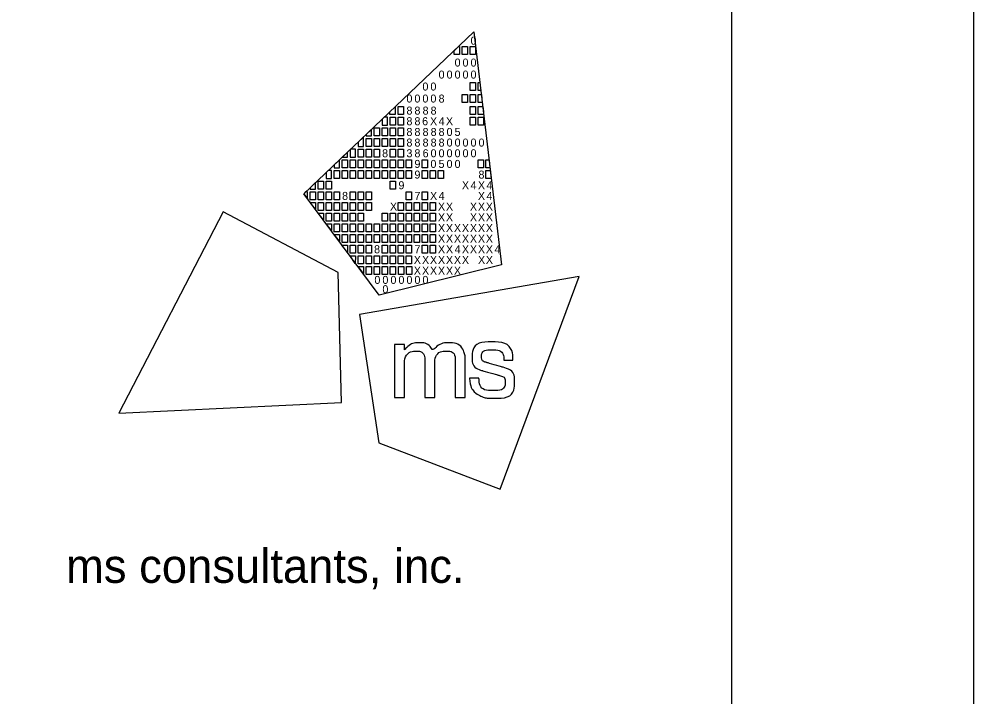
# Model space of a CAD drawing. Extents: x 0 to 34, y 0 to 22.
# Drawn here: x 32.03 to 34, y 2.714 to 4.112 of the extents above; entities that cross this region are included whole.
import ezdxf

# ---------------------------------------------------------------- set-up
doc = ezdxf.new("R2010")
doc.units = 0
for name, color, linetype in [('SH_Border', 7, 'Continuous'), ('SH_Cut_Line', 7, 'Continuous'), ('SH_Data', 7, 'Continuous')]:
    doc.layers.add(name, color=color, linetype=linetype)

msp = doc.modelspace()

# ---------------------------------------------------------------- linework, layer by layer
at = {"layer": 'SH_Border'}
msp.add_lwpolyline([(1.5, 21.5), (33.5, 21.5), (33.5, 0.5), (1.5, 0.5)], close=True, dxfattribs=at)
at = {"layer": 'SH_Cut_Line'}
msp.add_lwpolyline([(0, 0), (34, 0), (34, 22), (0, 22)], close=True, dxfattribs=at)
at = {"layer": 'SH_Data'}
for p, q in [((32.6175, 3.7519), (32.9688, 4.0861)), ((32.9688, 4.0861), (32.9688, 4.0861)), ((32.9688, 4.0861), (33.0253, 3.6052)), ((32.773, 3.543), (32.6175, 3.7519)), ((33.0253, 3.6052), (32.773, 3.543)), ((32.75, 3.5), (32.75, 3.5))]:
    msp.add_line(p, q, dxfattribs=at)
for points in [[(32.9279, 4.0472), (32.9369, 4.0558), (32.9389, 4.0558), (32.9389, 4.0393), (32.9279, 4.0393)], [(32.9444, 4.0558), (32.9554, 4.0558), (32.9554, 4.0393), (32.9444, 4.0393)], [(32.9609, 4.0558), (32.9719, 4.0558), (32.9719, 4.0393), (32.9609, 4.0393)], [(32.9606, 3.9815), (32.9716, 3.9815), (32.9716, 3.965), (32.9606, 3.965)], [(32.9771, 3.9815), (32.9811, 3.9815), (32.983, 3.965), (32.9771, 3.965)], [(32.9441, 3.9567), (32.9551, 3.9567), (32.9551, 3.9402), (32.9441, 3.9402)], [(32.9606, 3.9567), (32.9716, 3.9567), (32.9716, 3.9402), (32.9606, 3.9402)], [(32.9771, 3.9567), (32.984, 3.9567), (32.9859, 3.9402), (32.9771, 3.9402)], [(32.7953, 3.9211), (32.8064, 3.9316), (32.8064, 3.9154), (32.7953, 3.9154)], [(32.8123, 3.9319), (32.8233, 3.9319), (32.8233, 3.9154), (32.8123, 3.9154)], [(32.9606, 3.9319), (32.9716, 3.9319), (32.9716, 3.9154), (32.9606, 3.9154)], [(32.9771, 3.9319), (32.9869, 3.9319), (32.9881, 3.9218), (32.9881, 3.9154), (32.9771, 3.9154)], [(32.7958, 3.9099), (32.8068, 3.9099), (32.8068, 3.8934), (32.7958, 3.8934)], [(32.8123, 3.9099), (32.8233, 3.9099), (32.8233, 3.8934), (32.8123, 3.8934)], [(32.9606, 3.9099), (32.9716, 3.9099), (32.9716, 3.8934), (32.9606, 3.8934)], [(32.9771, 3.9099), (32.9881, 3.9099), (32.9881, 3.8934), (32.9771, 3.8934)], [(32.7627, 3.8879), (32.7737, 3.8879), (32.7737, 3.8714), (32.7627, 3.8714)], [(32.7793, 3.8879), (32.7903, 3.8879), (32.7903, 3.8714), (32.7793, 3.8714)], [(32.7958, 3.8879), (32.8068, 3.8879), (32.8068, 3.8714), (32.7958, 3.8714)], [(32.8123, 3.8879), (32.8233, 3.8879), (32.8233, 3.8714), (32.8123, 3.8714)], [(32.7462, 3.8659), (32.7572, 3.8659), (32.7572, 3.8494), (32.7462, 3.8494)], [(32.7627, 3.8659), (32.7737, 3.8659), (32.7737, 3.8494), (32.7627, 3.8494)], [(32.7793, 3.8659), (32.7903, 3.8659), (32.7903, 3.8494), (32.7793, 3.8494)], [(32.7958, 3.8659), (32.8068, 3.8659), (32.8068, 3.8494), (32.7958, 3.8494)], [(32.8123, 3.8659), (32.8233, 3.8659), (32.8233, 3.8494), (32.8123, 3.8494)], [(32.7297, 3.8439), (32.7407, 3.8439), (32.7407, 3.8273), (32.7297, 3.8273)], [(32.7462, 3.8439), (32.7572, 3.8439), (32.7572, 3.8273), (32.7462, 3.8273)], [(32.7627, 3.8439), (32.7737, 3.8439), (32.7737, 3.8273), (32.7627, 3.8273)], [(32.7958, 3.8439), (32.8068, 3.8439), (32.8068, 3.8273), (32.7958, 3.8273)], [(32.8123, 3.8439), (32.8233, 3.8439), (32.8233, 3.8273), (32.8123, 3.8273)], [(32.6967, 3.8218), (32.7077, 3.8218), (32.7077, 3.8053), (32.6967, 3.8053)], [(32.7132, 3.8218), (32.7242, 3.8218), (32.7242, 3.8053), (32.7132, 3.8053)], [(32.7297, 3.8218), (32.7407, 3.8218), (32.7407, 3.8053), (32.7297, 3.8053)], [(32.7462, 3.8218), (32.7572, 3.8218), (32.7572, 3.8053), (32.7462, 3.8053)], [(32.7627, 3.8218), (32.7737, 3.8218), (32.7737, 3.8053), (32.7627, 3.8053)], [(32.7793, 3.8218), (32.7903, 3.8218), (32.7903, 3.8053), (32.7793, 3.8053)], [(32.7958, 3.8218), (32.8068, 3.8218), (32.8068, 3.8053), (32.7958, 3.8053)], [(32.8123, 3.8218), (32.8233, 3.8218), (32.8233, 3.8053), (32.8123, 3.8053)], [(32.8288, 3.8218), (32.8398, 3.8218), (32.8398, 3.8053), (32.8288, 3.8053)], [(32.8618, 3.8218), (32.8728, 3.8218), (32.8728, 3.8053), (32.8618, 3.8053)], [(32.9771, 3.8218), (32.9881, 3.8218), (32.9881, 3.8053), (32.9771, 3.8053)], [(32.9935, 3.8218), (32.9998, 3.8218), (33.0018, 3.8053), (32.9935, 3.8053)], [(32.6802, 3.7998), (32.6912, 3.7998), (32.6912, 3.7833), (32.6802, 3.7833)], [(32.6967, 3.7998), (32.7077, 3.7998), (32.7077, 3.7833), (32.6967, 3.7833)], [(32.7132, 3.7998), (32.7242, 3.7998), (32.7242, 3.7833), (32.7132, 3.7833)], [(32.7297, 3.7998), (32.7407, 3.7998), (32.7407, 3.7833), (32.7297, 3.7833)], [(32.7462, 3.7998), (32.7572, 3.7998), (32.7572, 3.7833), (32.7462, 3.7833)], [(32.7627, 3.7998), (32.7737, 3.7998), (32.7737, 3.7833), (32.7627, 3.7833)], [(32.7793, 3.7998), (32.7903, 3.7998), (32.7903, 3.7833), (32.7793, 3.7833)], [(32.7958, 3.7998), (32.8068, 3.7998), (32.8068, 3.7833), (32.7958, 3.7833)], [(32.8123, 3.7998), (32.8233, 3.7998), (32.8233, 3.7833), (32.8123, 3.7833)], [(32.8288, 3.7998), (32.8398, 3.7998), (32.8398, 3.7833), (32.8288, 3.7833)], [(32.8618, 3.7998), (32.8728, 3.7998), (32.8728, 3.7833), (32.8618, 3.7833)], [(32.8783, 3.7998), (32.8893, 3.7998), (32.8893, 3.7833), (32.8783, 3.7833)], [(32.8947, 3.7998), (32.9057, 3.7998), (32.9057, 3.7833), (32.8947, 3.7833)], [(32.9935, 3.7998), (33.0024, 3.7998), (33.0044, 3.7833), (32.9935, 3.7833)], [(32.6471, 3.7778), (32.6581, 3.7778), (32.6581, 3.7613), (32.6471, 3.7613)], [(32.6637, 3.7778), (32.6747, 3.7778), (32.6747, 3.7613), (32.6637, 3.7613)], [(32.7958, 3.7778), (32.8068, 3.7778), (32.8068, 3.7613), (32.7958, 3.7613)], [(32.6306, 3.7558), (32.6416, 3.7558), (32.6416, 3.7393), (32.6306, 3.7393)], [(32.6471, 3.7558), (32.6581, 3.7558), (32.6581, 3.7393), (32.6471, 3.7393)], [(32.6637, 3.7558), (32.6747, 3.7558), (32.6747, 3.7393), (32.6637, 3.7393)], [(32.6802, 3.7558), (32.6912, 3.7558), (32.6912, 3.7393), (32.6802, 3.7393)], [(32.7132, 3.7558), (32.7242, 3.7558), (32.7242, 3.7393), (32.7132, 3.7393)], [(32.7297, 3.7558), (32.7407, 3.7558), (32.7407, 3.7393), (32.7297, 3.7393)], [(32.7462, 3.7558), (32.7572, 3.7558), (32.7572, 3.7393), (32.7462, 3.7393)], [(32.8288, 3.7558), (32.8398, 3.7558), (32.8398, 3.7393), (32.8288, 3.7393)], [(32.8618, 3.7558), (32.8728, 3.7558), (32.8728, 3.7393), (32.8618, 3.7393)], [(32.6306, 3.7338), (32.6416, 3.7338), (32.6416, 3.72)], [(32.6471, 3.7338), (32.6581, 3.7338), (32.6581, 3.7173), (32.6471, 3.7173)], [(32.6637, 3.7338), (32.6747, 3.7338), (32.6747, 3.7173), (32.6637, 3.7173)], [(32.6802, 3.7338), (32.6912, 3.7338), (32.6912, 3.7173), (32.6802, 3.7173)], [(32.6967, 3.7338), (32.7077, 3.7338), (32.7077, 3.7173), (32.6967, 3.7173)], [(32.7132, 3.7338), (32.7242, 3.7338), (32.7242, 3.7173), (32.7132, 3.7173)], [(32.7297, 3.7338), (32.7407, 3.7338), (32.7407, 3.7173), (32.7297, 3.7173)], [(32.7462, 3.7338), (32.7572, 3.7338), (32.7572, 3.7173), (32.7462, 3.7173)], [(32.8123, 3.7338), (32.8233, 3.7338), (32.8233, 3.7173), (32.8123, 3.7173)], [(32.8288, 3.7338), (32.8398, 3.7338), (32.8398, 3.7173), (32.8288, 3.7173)], [(32.8453, 3.7338), (32.8563, 3.7338), (32.8563, 3.7173), (32.8453, 3.7173)], [(32.8618, 3.7338), (32.8728, 3.7338), (32.8728, 3.7173), (32.8618, 3.7173)], [(32.8783, 3.7338), (32.8893, 3.7338), (32.8893, 3.7173), (32.8783, 3.7173)], [(32.6471, 3.7117), (32.6581, 3.7117), (32.6581, 3.698)], [(32.6637, 3.7117), (32.6747, 3.7117), (32.6747, 3.6952), (32.6637, 3.6952)], [(32.6802, 3.7117), (32.6912, 3.7117), (32.6912, 3.6952), (32.6802, 3.6952)], [(32.6967, 3.7117), (32.7077, 3.7117), (32.7077, 3.6952), (32.6967, 3.6952)], [(32.7132, 3.7117), (32.7242, 3.7117), (32.7242, 3.6952), (32.7132, 3.6952)], [(32.7297, 3.7117), (32.7407, 3.7117), (32.7407, 3.6952), (32.7297, 3.6952)], [(32.7793, 3.7117), (32.7903, 3.7117), (32.7903, 3.6952), (32.7793, 3.6952)], [(32.7958, 3.7117), (32.8068, 3.7117), (32.8068, 3.6952), (32.7958, 3.6952)], [(32.8123, 3.7117), (32.8233, 3.7117), (32.8233, 3.6952), (32.8123, 3.6952)], [(32.8288, 3.7117), (32.8398, 3.7117), (32.8398, 3.6952), (32.8288, 3.6952)], [(32.8453, 3.7117), (32.8563, 3.7117), (32.8563, 3.6952), (32.8453, 3.6952)], [(32.8618, 3.7117), (32.8728, 3.7117), (32.8728, 3.6952), (32.8618, 3.6952)], [(32.8783, 3.7117), (32.8893, 3.7117), (32.8893, 3.6952), (32.8783, 3.6952)], [(32.6637, 3.6897), (32.6747, 3.6897), (32.6747, 3.676)], [(32.6747, 3.6897), (32.6747, 3.6897), (32.6747, 3.6897)], [(32.6802, 3.6897), (32.6912, 3.6897), (32.6912, 3.6732), (32.6802, 3.6732)], [(32.6967, 3.6897), (32.7077, 3.6897), (32.7077, 3.6732), (32.6967, 3.6732)], [(32.7132, 3.6897), (32.7242, 3.6897), (32.7242, 3.6732), (32.7132, 3.6732)], [(32.7297, 3.6897), (32.7407, 3.6897), (32.7407, 3.6732), (32.7297, 3.6732)], [(32.7462, 3.6897), (32.7572, 3.6897), (32.7572, 3.6732), (32.7462, 3.6732)], [(32.7627, 3.6897), (32.7737, 3.6897), (32.7737, 3.6732), (32.7627, 3.6732)], [(32.7793, 3.6897), (32.7903, 3.6897), (32.7903, 3.6732), (32.7793, 3.6732)], [(32.7958, 3.6897), (32.8068, 3.6897), (32.8068, 3.6732), (32.7958, 3.6732)], [(32.8123, 3.6897), (32.8233, 3.6897), (32.8233, 3.6732), (32.8123, 3.6732)], [(32.8288, 3.6897), (32.8398, 3.6897), (32.8398, 3.6732), (32.8288, 3.6732)], [(32.8453, 3.6897), (32.8563, 3.6897), (32.8563, 3.6732), (32.8453, 3.6732)], [(32.8618, 3.6897), (32.8728, 3.6897), (32.8728, 3.6732), (32.8618, 3.6732)], [(32.8783, 3.6897), (32.8893, 3.6897), (32.8893, 3.6732), (32.8783, 3.6732)], [(32.6802, 3.6677), (32.6912, 3.6677), (32.6912, 3.654)], [(32.6967, 3.6677), (32.7077, 3.6677), (32.7077, 3.6512), (32.6967, 3.6512)], [(32.7132, 3.6677), (32.7242, 3.6677), (32.7242, 3.6512), (32.7132, 3.6512)], [(32.7297, 3.6677), (32.7407, 3.6677), (32.7407, 3.6512), (32.7297, 3.6512)], [(32.7462, 3.6677), (32.7572, 3.6677), (32.7572, 3.6512), (32.7462, 3.6512)], [(32.7627, 3.6677), (32.7737, 3.6677), (32.7737, 3.6512), (32.7627, 3.6512)], [(32.7793, 3.6677), (32.7903, 3.6677), (32.7903, 3.6512), (32.7793, 3.6512)], [(32.7958, 3.6677), (32.8068, 3.6677), (32.8068, 3.6512), (32.7958, 3.6512)], [(32.8123, 3.6677), (32.8233, 3.6677), (32.8233, 3.6512), (32.8123, 3.6512)], [(32.8288, 3.6677), (32.8398, 3.6677), (32.8398, 3.6512), (32.8288, 3.6512)], [(32.8453, 3.6677), (32.8563, 3.6677), (32.8563, 3.6512), (32.8453, 3.6512)], [(32.8618, 3.6677), (32.8728, 3.6677), (32.8728, 3.6512), (32.8618, 3.6512)], [(32.8783, 3.6677), (32.8893, 3.6677), (32.8893, 3.6512), (32.8783, 3.6512)], [(32.7077, 3.6305), (32.6965, 3.6457), (32.7077, 3.6457)], [(32.7132, 3.6457), (32.7242, 3.6457), (32.7242, 3.6292), (32.7132, 3.6292)], [(32.7297, 3.6457), (32.7407, 3.6457), (32.7407, 3.6292), (32.7297, 3.6292)], [(32.7462, 3.6457), (32.7572, 3.6457), (32.7572, 3.6292), (32.7462, 3.6292)], [(32.7793, 3.6457), (32.7903, 3.6457), (32.7903, 3.6292), (32.7793, 3.6292)], [(32.7958, 3.6457), (32.8068, 3.6457), (32.8068, 3.6292), (32.7958, 3.6292)], [(32.8123, 3.6457), (32.8233, 3.6457), (32.8233, 3.6292), (32.8123, 3.6292)], [(32.8288, 3.6457), (32.8398, 3.6457), (32.8398, 3.6292), (32.8288, 3.6292)], [(32.8618, 3.6457), (32.8728, 3.6457), (32.8728, 3.6292), (32.8618, 3.6292)], [(32.8783, 3.6457), (32.8893, 3.6457), (32.8893, 3.6292), (32.8783, 3.6292)], [(32.724, 3.6082), (32.7132, 3.6237), (32.7242, 3.6237)], [(32.7297, 3.6237), (32.7407, 3.6237), (32.7407, 3.6072), (32.7297, 3.6072)], [(32.7462, 3.6237), (32.7572, 3.6237), (32.7572, 3.6072), (32.7462, 3.6072)], [(32.7627, 3.6237), (32.7737, 3.6237), (32.7737, 3.6072), (32.7627, 3.6072)], [(32.7793, 3.6237), (32.7903, 3.6237), (32.7903, 3.6072), (32.7793, 3.6072)], [(32.7958, 3.6237), (32.8068, 3.6237), (32.8068, 3.6072), (32.7958, 3.6072)], [(32.8123, 3.6237), (32.8233, 3.6237), (32.8233, 3.6072), (32.8123, 3.6072)], [(32.8288, 3.6237), (32.8398, 3.6237), (32.8398, 3.6072), (32.8288, 3.6072)], [(32.7302, 3.6017), (32.7407, 3.6017), (32.7408, 3.5875)], [(32.7463, 3.6017), (32.7573, 3.6017), (32.7573, 3.5852), (32.7463, 3.5852)], [(32.763, 3.6017), (32.774, 3.6017), (32.774, 3.5852), (32.763, 3.5852)], [(32.7794, 3.6017), (32.7904, 3.6017), (32.7904, 3.5852), (32.7794, 3.5852)], [(32.796, 3.6017), (32.807, 3.6017), (32.807, 3.5852), (32.796, 3.5852)], [(32.8129, 3.6017), (32.8239, 3.6017), (32.8239, 3.5851), (32.8129, 3.5851)], [(32.8296, 3.6017), (32.8406, 3.6017), (32.8406, 3.5851), (32.8296, 3.5851)]]:
    msp.add_lwpolyline(points, close=True, dxfattribs=at)
for points in [[(32.7903, 3.9099), (32.7836, 3.9099), (32.7793, 3.9058), (32.7793, 3.8934), (32.7903, 3.8934), (32.7903, 3.9099)], [(32.7572, 3.8849), (32.7462, 3.8744), (32.7462, 3.8714), (32.7572, 3.8714), (32.7572, 3.8849)], [(32.7407, 3.8691), (32.7297, 3.8587), (32.7297, 3.8494), (32.7407, 3.8494), (32.7407, 3.8691)], [(32.7242, 3.8439), (32.7141, 3.8439), (32.7132, 3.843), (32.7132, 3.8273), (32.7242, 3.8273), (32.7242, 3.8439)], [(32.6912, 3.822), (32.6802, 3.8115), (32.6802, 3.8053), (32.6912, 3.8053), (32.6912, 3.822)], [(32.7077, 3.8377), (32.6968, 3.8273), (32.7077, 3.8273), (32.7077, 3.8377)], [(32.6747, 3.7998), (32.6679, 3.7998), (32.6637, 3.7958), (32.6637, 3.7833), (32.6747, 3.7833), (32.6747, 3.7998)], [(32.6416, 3.7749), (32.6306, 3.7644), (32.6306, 3.7613), (32.6416, 3.7613), (32.6416, 3.7749)], [(32.6251, 3.7558), (32.6216, 3.7558), (32.6175, 3.7519), (32.6251, 3.7417), (32.6251, 3.7558)], [(32.4512, 3.7149), (32.2359, 3.2988), (32.6956, 3.3215), (32.6884, 3.5892), (32.4512, 3.7149)], [(33.0229, 3.1422), (33.1859, 3.5814), (32.7324, 3.5029), (32.7722, 3.2381), (33.0229, 3.1422)]]:
    msp.add_lwpolyline(points, dxfattribs=at)
for points in [[(32.8048, 3.3315), (32.8048, 3.3315), (32.8048, 3.4409), (32.8048, 3.4409), (32.8048, 3.4409), (32.8255, 3.4409), (32.8255, 3.4409), (32.8255, 3.4409), (32.8255, 3.4297), (32.8255, 3.4297), (32.8346, 3.4399), (32.8457, 3.4445), (32.8555, 3.4445), (32.8688, 3.4445), (32.8791, 3.4372), (32.8837, 3.4266), (32.8915, 3.4381), (32.905, 3.4446), (32.9166, 3.4446), (32.9325, 3.4446), (32.9451, 3.435), (32.9494, 3.4213), (32.9494, 3.4212), (32.9494, 3.4212), (32.9494, 3.4212), (32.9501, 3.419), (32.9506, 3.4172), (32.9506, 3.4071), (32.9506, 3.4071), (32.9506, 3.3314), (32.9506, 3.3314), (32.9506, 3.3314), (32.9303, 3.3314), (32.9303, 3.3314), (32.9303, 3.3314), (32.9303, 3.4048), (32.9303, 3.4048), (32.9303, 3.4201), (32.9219, 3.4274), (32.911, 3.4274), (32.8995, 3.4274), (32.8879, 3.4171), (32.8879, 3.4001), (32.8879, 3.4001), (32.8879, 3.3315), (32.8879, 3.3315), (32.8879, 3.3315), (32.8674, 3.3315), (32.8674, 3.3315), (32.8674, 3.3315), (32.8674, 3.4059), (32.8674, 3.4059), (32.8674, 3.4203), (32.8588, 3.4274), (32.8496, 3.4274), (32.8384, 3.4274), (32.8254, 3.417), (32.8254, 3.3962), (32.8254, 3.3962), (32.8254, 3.3315), (32.8254, 3.3315), (32.8254, 3.3315), (32.8048, 3.3315), (32.8048, 3.3315)], [(32.9595, 3.3709), (32.9595, 3.3709), (32.9595, 3.3717), (32.9595, 3.3717), (32.9595, 3.3717), (32.9603, 3.3717), (32.9603, 3.3717), (32.9603, 3.3717), (32.9783, 3.3717), (32.9783, 3.3717), (32.9783, 3.3717), (32.9789, 3.3717), (32.9789, 3.3717), (32.9789, 3.3717), (32.979, 3.371), (32.979, 3.371), (32.9803, 3.3554), (32.9887, 3.346), (33.009, 3.346), (33.0273, 3.346), (33.0333, 3.3554), (33.0333, 3.3631), (33.0333, 3.3732), (33.0256, 3.3758), (33.0175, 3.378), (33.0175, 3.378), (32.987, 3.3867), (32.987, 3.3867), (32.972, 3.3909), (32.9648, 3.4019), (32.9648, 3.4142), (32.9648, 3.4303), (32.9768, 3.4462), (33.0052, 3.4462), (33.0348, 3.4462), (33.0489, 3.4285), (33.0489, 3.4095), (33.0489, 3.4095), (33.0489, 3.4087), (33.0489, 3.4087), (33.0489, 3.4087), (33.0482, 3.4087), (33.0482, 3.4087), (33.0482, 3.4087), (33.0312, 3.4087), (33.0312, 3.4087), (33.0312, 3.4087), (33.0305, 3.4087), (33.0305, 3.4087), (33.0305, 3.4087), (33.0305, 3.4094), (33.0305, 3.4094), (33.0301, 3.4208), (33.0226, 3.43), (33.0056, 3.43), (32.9891, 3.43), (32.9843, 3.4218), (32.9843, 3.4157), (32.9843, 3.4108), (32.9869, 3.4059), (32.9959, 3.4033), (32.9959, 3.4033), (33.0255, 3.3948), (33.0255, 3.3948), (33.0462, 3.3889), (33.0527, 3.3777), (33.0527, 3.3639), (33.0527, 3.3462), (33.041, 3.3298), (33.0087, 3.3298), (32.9952, 3.3298), (32.9877, 3.3321), (32.9823, 3.3348), (32.969, 3.3414), (32.9609, 3.3536), (32.9595, 3.3709)]]:
    msp.add_open_spline(points, degree=3, dxfattribs=at)

# ---------------------------------------------------------------- texts
for s, height, p in [('0', 0.0165, (32.9617, 4.0597)), ('0', 0.0165, (32.9288, 4.0145)), ('0', 0.0165, (32.9452, 4.0145)), ('0', 0.0165, (32.9617, 4.0145)), ('0', 0.0165, (32.8958, 3.9897)), ('0', 0.0165, (32.9123, 3.9897)), ('0', 0.0165, (32.9288, 3.9897)), ('0', 0.0165, (32.9452, 3.9897)), ('0', 0.0165, (32.9617, 3.9897)), ('0', 0.0165, (32.8625, 3.965)), ('0', 0.0165, (32.879, 3.965)), ('0', 0.0165, (32.8295, 3.9402)), ('0', 0.0165, (32.846, 3.9402)), ('0', 0.0165, (32.8625, 3.9402)), ('0', 0.0165, (32.879, 3.9402)), ('8', 0.0165, (32.8958, 3.9402)), ('8', 0.0165, (32.8295, 3.9154)), ('8', 0.0165, (32.846, 3.9154)), ('8', 0.0165, (32.8628, 3.9154)), ('8', 0.0165, (32.8793, 3.9154)), ('8', 0.0165, (32.8295, 3.8934)), ('8', 0.0165, (32.846, 3.8934)), ('6', 0.0165, (32.8618, 3.8934)), ('X', 0.0165, (32.8781, 3.8934)), ('4', 0.0165, (32.8958, 3.8934)), ('X', 0.0165, (32.911, 3.8934)), ('8', 0.0165, (32.8295, 3.8713)), ('8', 0.0165, (32.846, 3.8713)), ('8', 0.0165, (32.8628, 3.8713)), ('8', 0.0165, (32.8794, 3.8713)), ('8', 0.0165, (32.8958, 3.8713)), ('0', 0.0165, (32.9123, 3.8713)), ('5', 0.0165, (32.9287, 3.8713)), ('8', 0.0165, (32.8295, 3.8494)), ('8', 0.0165, (32.846, 3.8494)), ('8', 0.0165, (32.8628, 3.8494)), ('8', 0.0165, (32.8794, 3.8494)), ('8', 0.0165, (32.8958, 3.8494)), ('0', 0.0165, (32.9123, 3.8494)), ('0', 0.0165, (32.9288, 3.8494)), ('0', 0.0165, (32.9452, 3.8494)), ('0', 0.0165, (32.9617, 3.8494)), ('0', 0.0165, (32.9782, 3.8494)), ('8', 0.0165, (32.7793, 3.8273)), ('3', 0.0165, (32.8295, 3.8273)), ('8', 0.0165, (32.846, 3.8273)), ('6', 0.0165, (32.8629, 3.8273)), ('0', 0.0165, (32.8793, 3.8273)), ('0', 0.0165, (32.8958, 3.8273)), ('0', 0.0165, (32.9123, 3.8273)), ('0', 0.0165, (32.9288, 3.8273)), ('0', 0.0165, (32.9452, 3.8273)), ('0', 0.0165, (32.9617, 3.8273)), ('9', 0.0165, (32.846, 3.8053)), ('0', 0.0165, (32.879, 3.8053)), ('5', 0.0165, (32.8957, 3.8053)), ('0', 0.0165, (32.9123, 3.8053)), ('0', 0.0165, (32.9288, 3.8053)), ('9', 0.0165, (32.846, 3.7833)), ('8', 0.0165, (32.9781, 3.7833)), ('9', 0.0165, (32.813, 3.7613)), ('X', 0.0165, (32.9439, 3.7613)), ('4', 0.0165, (32.9617, 3.7613)), ('X', 0.0165, (32.9769, 3.7613)), ('4', 0.0165, (32.9946, 3.7613)), ('8', 0.0165, (32.6967, 3.7393)), ('7', 0.0165, (32.846, 3.7393)), ('X', 0.0165, (32.8781, 3.7393)), ('4', 0.0165, (32.8958, 3.7393)), ('X', 0.0165, (32.9769, 3.7393)), ('4', 0.0165, (32.9946, 3.7393)), ('X', 0.0165, (32.7955, 3.7173)), ('X', 0.0165, (32.8945, 3.7173)), ('X', 0.0165, (32.911, 3.7173)), ('X', 0.0165, (32.9604, 3.7173)), ('X', 0.0165, (32.9769, 3.7173)), ('X', 0.0165, (32.9933, 3.7173)), ('X', 0.0165, (32.8945, 3.6952)), ('X', 0.0165, (32.911, 3.6952)), ('X', 0.0165, (32.9604, 3.6952)), ('X', 0.0165, (32.9769, 3.6952)), ('X', 0.0165, (32.9933, 3.6952)), ('X', 0.0165, (32.8945, 3.6732)), ('X', 0.0165, (32.911, 3.6732)), ('X', 0.0165, (32.9274, 3.6732)), ('X', 0.0165, (32.9439, 3.6732)), ('X', 0.0165, (32.9604, 3.6732)), ('X', 0.0165, (32.9769, 3.6732)), ('X', 0.0165, (32.9933, 3.6732)), ('X', 0.0165, (32.8945, 3.6512)), ('X', 0.0165, (32.911, 3.6512)), ('X', 0.0165, (32.9274, 3.6512)), ('X', 0.0165, (32.9439, 3.6512)), ('X', 0.0165, (32.9604, 3.6512)), ('X', 0.0165, (32.9769, 3.6512)), ('X', 0.0165, (32.9933, 3.6512)), ('8', 0.0165, (32.7627, 3.6292)), ('7', 0.0165, (32.846, 3.6292)), ('X', 0.0165, (32.8945, 3.6292)), ('X', 0.0165, (32.911, 3.6292)), ('4', 0.0165, (32.9288, 3.6292)), ('X', 0.0165, (32.9439, 3.6292)), ('X', 0.0165, (32.9604, 3.6292)), ('X', 0.0165, (32.9769, 3.6292)), ('X', 0.0165, (32.9933, 3.6292)), ('4', 0.0165, (33.0111, 3.6292)), ('X', 0.0165, (32.8447, 3.6072)), ('X', 0.0165, (32.8616, 3.6072)), ('X', 0.0165, (32.878, 3.6072)), ('X', 0.0165, (32.8945, 3.6072)), ('X', 0.0165, (32.911, 3.6072)), ('X', 0.0165, (32.9274, 3.6072)), ('X', 0.0165, (32.9439, 3.6072)), ('X', 0.0165, (32.9771, 3.6072)), ('X', 0.0165, (32.9933, 3.6072)), ('X', 0.0165, (32.8447, 3.5851)), ('X', 0.0165, (32.8616, 3.5851)), ('X', 0.0165, (32.878, 3.5851)), ('X', 0.0165, (32.8945, 3.5851)), ('X', 0.0165, (32.911, 3.5851)), ('X', 0.0165, (32.9274, 3.5851)), ('0', 0.0165, (32.7634, 3.5659)), ('0', 0.0165, (32.7799, 3.5659)), ('0', 0.0165, (32.7965, 3.5659)), ('0', 0.0165, (32.813, 3.5659)), ('0', 0.0165, (32.8295, 3.5659)), ('0', 0.0165, (32.846, 3.5659)), ('0', 0.0165, (32.8625, 3.5659)), ('0', 0.0165, (32.7799, 3.5467)), ('ms consultants, inc.', 0.07, (32.1273, 2.9489))]:
    msp.add_text(s, height=height, rotation=360, dxfattribs=at).set_placement(p)

doc.saveas('drawing.dxf')
